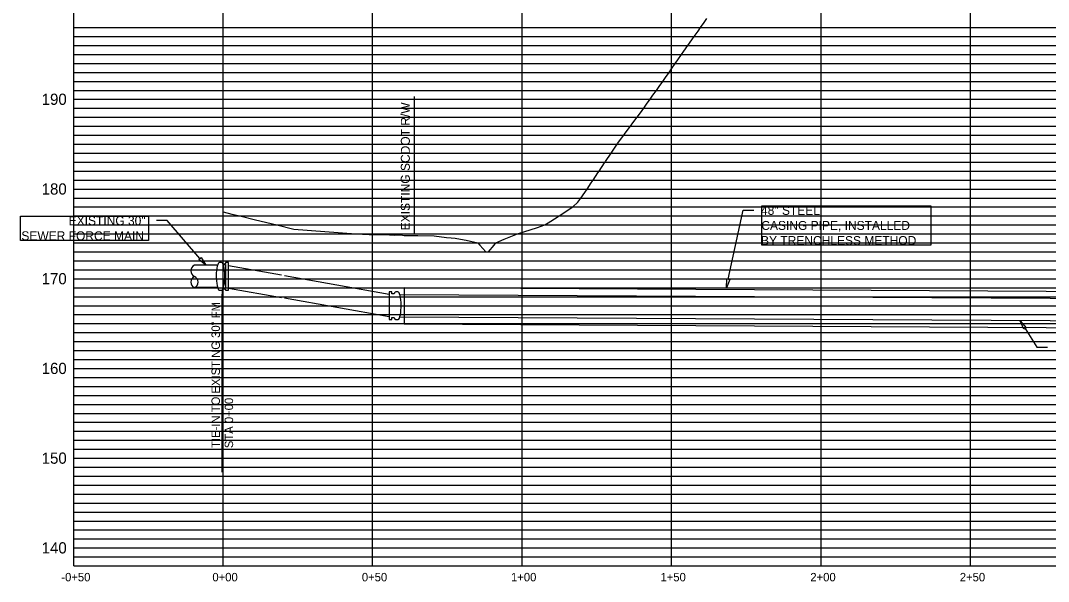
# Model space of a CAD drawing. Extents: x 1961446 to 1965364, y 798002 to 798458.
# Drawn here: x 1964684.5 to 1965028.3, y 798002.3 to 798189.8 of the extents above; entities that cross this region are included whole.
import ezdxf

# ---------------------------------------------------------------- set-up
doc = ezdxf.new("R2010")
doc.units = 0
for name, color, linetype in [('_C3D-PRSR-ANNO', 7, 'Continuous'), ('_C3D-PRSR-PIPE-NEW 30 FM', 7, 'Continuous'), ('C-ANNO-SUBT', 7, 'Continuous'), ('C-DOMW-MAIN-PIPE', 7, 'Continuous'), ('C-GRID-MEDI', 7, 'Continuous'), ('C-GRID-THIN', 7, 'Continuous'), ('C-PROF-EXST', 7, 'Continuous'), ('C-SSWR-FMAN-FTTG', 7, 'Continuous'), ('C-SSWR-FMAN-PIPE', 7, 'Continuous'), ('C-UTIL-FITT-ANNO', 7, 'Continuous'), ('RD_EX_RW', 7, 'Continuous')]:
    doc.layers.add(name, color=color, linetype=linetype)

msp = doc.modelspace()

# ---------------------------------------------------------------- linework, layer by layer
at = {"layer": '_C3D-PRSR-ANNO'}
for points in [[(1964750.23, 798108.01), (1964742.68, 798108.01)], [(1964750.32, 798100.51), (1964742.68, 798100.51)]]:
    msp.add_lwpolyline(points, dxfattribs=at)
for centre, start, end in [((1964743.5, 798106.14), 113.818, 246.182), ((1964743.5, 798102.39), 113.818, 246.182), ((1964741.85, 798102.39), 293.818, 66.182)]:
    msp.add_arc(centre, 2.05, start, end, dxfattribs=at)
at = {"layer": '_C3D-PRSR-PIPE-NEW 30 FM'}
msp.add_lwpolyline([(1964812.85, 798088.45), (1965222.8, 798086.11), (1965222.8, 798098.11), (1964812.85, 798100.45)], close=True, dxfattribs=at)
at = {"layer": 'C-DOMW-MAIN-PIPE'}
for points in [[(1964754.01, 798107.87), (1964771.76, 798104.74)], [(1964772.8, 798104.56), (1964807.75, 798098.38)], [(1964754.01, 798100.37), (1964771.76, 798097.24)], [(1964772.8, 798097.06), (1964807.75, 798090.88)]]:
    msp.add_lwpolyline(points, dxfattribs=at)
at = {"layer": 'C-GRID-MEDI'}
for points in [[(1964702.28, 798007.48), (1964702.28, 798313.48)], [(1964702.28, 798007.48), (1964702.28, 798313.48)], [(1964752.28, 798007.48), (1964752.28, 798313.48)], [(1964802.28, 798007.48), (1964802.28, 798313.48)], [(1964852.28, 798007.48), (1964852.28, 798313.48)], [(1964902.28, 798007.48), (1964902.28, 798313.48)], [(1964952.28, 798007.48), (1964952.28, 798313.48)], [(1965002.28, 798007.48), (1965002.28, 798313.48)], [(1964702.28, 798163.48), (1964752.28, 798163.48)], [(1964752.28, 798163.48), (1965283.11, 798163.48)], [(1964702.28, 798133.48), (1964752.28, 798133.48)], [(1964752.28, 798133.48), (1965283.11, 798133.48)], [(1964702.28, 798103.48), (1964752.28, 798103.48)], [(1964752.28, 798103.48), (1965283.11, 798103.48)], [(1964702.28, 798073.48), (1964752.28, 798073.48)], [(1964752.28, 798073.48), (1965283.11, 798073.48)], [(1964702.28, 798043.48), (1964752.28, 798043.48)], [(1964752.28, 798043.48), (1965283.11, 798043.48)], [(1964702.28, 798013.48), (1964752.28, 798013.48)], [(1964752.28, 798013.48), (1965283.11, 798013.48)], [(1964702.28, 798007.48), (1964752.28, 798007.48)], [(1964702.28, 798007.48), (1965352.28, 798007.48)], [(1964752.28, 798007.48), (1965283.11, 798007.48)]]:
    msp.add_lwpolyline(points, dxfattribs=at)
at = {"layer": 'C-GRID-THIN'}
for points in [[(1964702.28, 798187.48), (1964752.28, 798187.48)], [(1964752.28, 798187.48), (1965283.11, 798187.48)], [(1964702.28, 798184.48), (1964752.28, 798184.48)], [(1964752.28, 798184.48), (1965283.11, 798184.48)], [(1964702.28, 798181.48), (1964752.28, 798181.48)], [(1964752.28, 798181.48), (1965283.11, 798181.48)], [(1964702.28, 798178.48), (1964752.28, 798178.48)], [(1964752.28, 798178.48), (1965283.11, 798178.48)], [(1964702.28, 798175.48), (1964752.28, 798175.48)], [(1964752.28, 798175.48), (1965283.11, 798175.48)], [(1964702.28, 798172.48), (1964752.28, 798172.48)], [(1964752.28, 798172.48), (1965283.11, 798172.48)], [(1964702.28, 798169.48), (1964752.28, 798169.48)], [(1964752.28, 798169.48), (1965283.11, 798169.48)], [(1964702.28, 798166.48), (1964752.28, 798166.48)], [(1964752.28, 798166.48), (1965283.11, 798166.48)], [(1964702.28, 798160.48), (1964752.28, 798160.48)], [(1964752.28, 798160.48), (1965283.11, 798160.48)], [(1964702.28, 798157.48), (1964752.28, 798157.48)], [(1964752.28, 798157.48), (1965283.11, 798157.48)], [(1964702.28, 798154.48), (1964752.28, 798154.48)], [(1964752.28, 798154.48), (1965283.11, 798154.48)], [(1964702.28, 798151.48), (1964752.28, 798151.48)], [(1964752.28, 798151.48), (1965283.11, 798151.48)], [(1964702.28, 798148.48), (1964752.28, 798148.48)], [(1964752.28, 798148.48), (1965283.11, 798148.48)], [(1964702.28, 798145.48), (1964752.28, 798145.48)], [(1964752.28, 798145.48), (1965283.11, 798145.48)], [(1964702.28, 798142.48), (1964752.28, 798142.48)], [(1964702.28, 798139.48), (1964752.28, 798139.48)], [(1964752.28, 798142.48), (1965283.11, 798142.48)], [(1964752.28, 798139.48), (1965283.11, 798139.48)], [(1964702.28, 798136.48), (1964752.28, 798136.48)], [(1964752.28, 798136.48), (1965283.11, 798136.48)], [(1964702.28, 798130.48), (1964752.28, 798130.48)], [(1964752.28, 798130.48), (1965283.11, 798130.48)], [(1964702.28, 798127.48), (1964752.28, 798127.48)], [(1964752.28, 798127.48), (1965283.11, 798127.48)], [(1964702.28, 798124.48), (1964752.28, 798124.48)], [(1964752.28, 798124.48), (1965283.11, 798124.48)], [(1964702.28, 798121.48), (1964752.28, 798121.48)], [(1964752.28, 798121.48), (1965283.11, 798121.48)], [(1964702.28, 798118.48), (1964752.28, 798118.48)], [(1964702.28, 798115.48), (1964752.28, 798115.48)], [(1964752.28, 798118.48), (1965283.11, 798118.48)], [(1964752.28, 798115.48), (1965283.11, 798115.48)], [(1964702.28, 798112.48), (1964752.28, 798112.48)], [(1964752.28, 798112.48), (1965283.11, 798112.48)], [(1964702.28, 798109.48), (1964752.28, 798109.48)], [(1964752.28, 798109.48), (1965283.11, 798109.48)], [(1964702.28, 798106.48), (1964752.28, 798106.48)], [(1964752.28, 798106.48), (1965283.11, 798106.48)], [(1964702.28, 798100.48), (1964752.28, 798100.48)], [(1964752.28, 798100.48), (1965283.11, 798100.48)], [(1964702.28, 798097.48), (1964752.28, 798097.48)], [(1964702.28, 798094.48), (1964752.28, 798094.48)], [(1964752.28, 798097.48), (1965283.11, 798097.48)], [(1964752.28, 798094.48), (1965283.11, 798094.48)], [(1964702.28, 798091.48), (1964752.28, 798091.48)], [(1964752.28, 798091.48), (1965283.11, 798091.48)], [(1964702.28, 798088.48), (1964752.28, 798088.48)], [(1964752.28, 798088.48), (1965283.11, 798088.48)], [(1964702.28, 798085.48), (1964752.28, 798085.48)], [(1964752.28, 798085.48), (1965283.11, 798085.48)], [(1964702.28, 798082.48), (1964752.28, 798082.48)], [(1964752.28, 798082.48), (1965283.11, 798082.48)], [(1964702.28, 798079.48), (1964752.28, 798079.48)], [(1964752.28, 798079.48), (1965283.11, 798079.48)], [(1964702.28, 798076.48), (1964752.28, 798076.48)], [(1964752.28, 798076.48), (1965283.11, 798076.48)], [(1964702.28, 798070.48), (1964752.28, 798070.48)], [(1964752.28, 798070.48), (1965283.11, 798070.48)], [(1964702.28, 798067.48), (1964752.28, 798067.48)], [(1964752.28, 798067.48), (1965283.11, 798067.48)], [(1964702.28, 798064.48), (1964752.28, 798064.48)], [(1964752.28, 798064.48), (1965283.11, 798064.48)], [(1964702.28, 798061.48), (1964752.28, 798061.48)], [(1964752.28, 798061.48), (1965283.11, 798061.48)], [(1964702.28, 798058.48), (1964752.28, 798058.48)], [(1964752.28, 798058.48), (1965283.11, 798058.48)], [(1964702.28, 798055.48), (1964752.28, 798055.48)], [(1964752.28, 798055.48), (1965283.11, 798055.48)], [(1964702.28, 798052.48), (1964752.28, 798052.48)], [(1964752.28, 798052.48), (1965283.11, 798052.48)], [(1964702.28, 798049.48), (1964752.28, 798049.48)], [(1964702.28, 798046.48), (1964752.28, 798046.48)], [(1964752.28, 798049.48), (1965283.11, 798049.48)], [(1964752.28, 798046.48), (1965283.11, 798046.48)], [(1964702.28, 798040.48), (1964752.28, 798040.48)], [(1964752.28, 798040.48), (1965283.11, 798040.48)], [(1964702.28, 798037.48), (1964752.28, 798037.48)], [(1964752.28, 798037.48), (1965283.11, 798037.48)], [(1964702.28, 798034.48), (1964752.28, 798034.48)], [(1964752.28, 798034.48), (1965283.11, 798034.48)], [(1964702.28, 798031.48), (1964752.28, 798031.48)], [(1964752.28, 798031.48), (1965283.11, 798031.48)], [(1964702.28, 798028.48), (1964752.28, 798028.48)], [(1964752.28, 798028.48), (1965283.11, 798028.48)], [(1964702.28, 798025.48), (1964752.28, 798025.48)], [(1964702.28, 798022.48), (1964752.28, 798022.48)], [(1964752.28, 798025.48), (1965283.11, 798025.48)], [(1964752.28, 798022.48), (1965283.11, 798022.48)], [(1964702.28, 798019.48), (1964752.28, 798019.48)], [(1964752.28, 798019.48), (1965283.11, 798019.48)], [(1964702.28, 798016.48), (1964752.28, 798016.48)], [(1964752.28, 798016.48), (1965283.11, 798016.48)], [(1964702.28, 798010.48), (1964752.28, 798010.48)], [(1964752.28, 798010.48), (1965283.11, 798010.48)]]:
    msp.add_lwpolyline(points, dxfattribs=at)
at = {"layer": 'C-PROF-EXST'}
for points in [[(1964911.14, 798186.3), (1964911.97, 798187.48)], [(1964911.97, 798187.48), (1964913.14, 798189.15)], [(1964913.14, 798189.15), (1964914.08, 798190.48)], [(1964909.09, 798183.39), (1964909.86, 798184.48)], [(1964909.86, 798184.48), (1964911.14, 798186.3)], [(1964906.39, 798179.56), (1964907.75, 798181.48)], [(1964907.75, 798181.48), (1964909.09, 798183.39)], [(1964904.34, 798176.64), (1964905.64, 798178.48)], [(1964905.64, 798178.48), (1964906.39, 798179.56)], [(1964901.41, 798172.48), (1964902.27, 798173.7)], [(1964902.27, 798173.7), (1964903.52, 798175.48)], [(1964903.52, 798175.48), (1964904.34, 798176.64)], [(1964899.3, 798169.48), (1964900.19, 798170.75)], [(1964900.19, 798170.75), (1964901.41, 798172.48)], [(1964897.19, 798166.48), (1964898.11, 798167.79)], [(1964898.11, 798167.79), (1964899.3, 798169.48)], [(1964893.92, 798161.84), (1964895.08, 798163.48)], [(1964895.08, 798163.48), (1964896.02, 798164.82)], [(1964896.02, 798164.82), (1964897.19, 798166.48)], [(1964891.82, 798158.94), (1964892.97, 798160.48)], [(1964892.97, 798160.48), (1964893.92, 798161.84)], [(1964889.35, 798155.57), (1964890.79, 798157.48)], [(1964890.79, 798157.48), (1964891.82, 798158.94)], [(1964886.77, 798152.13), (1964888.54, 798154.48)], [(1964888.54, 798154.48), (1964889.35, 798155.57)], [(1964884.18, 798148.66), (1964886.29, 798151.48)], [(1964886.29, 798151.48), (1964886.77, 798152.13)], [(1964882.04, 798145.48), (1964884.03, 798148.44)], [(1964884.03, 798148.44), (1964884.06, 798148.48)], [(1964884.06, 798148.48), (1964884.18, 798148.66)], [(1964880.03, 798142.48), (1964880.19, 798142.73)], [(1964880.19, 798142.73), (1964882.04, 798145.48)], [(1964877.61, 798138.87), (1964878.02, 798139.48)], [(1964878.02, 798139.48), (1964879.87, 798142.24)], [(1964879.87, 798142.24), (1964880.03, 798142.48)], [(1964875.4, 798135.59), (1964876, 798136.48)], [(1964876, 798136.48), (1964877.61, 798138.87)], [(1964871.97, 798130.48), (1964873.24, 798132.38)], [(1964873.24, 798132.38), (1964873.99, 798133.48)], [(1964873.99, 798133.48), (1964875.4, 798135.59)], [(1964869.25, 798127.48), (1964870.86, 798129.11)], [(1964870.86, 798129.11), (1964871.97, 798130.48)], [(1964752.28, 798125.83), (1964755.18, 798125.13)], [(1964865.04, 798124.72), (1964869.25, 798127.48)], [(1964755.18, 798125.13), (1964757.83, 798124.48)], [(1964757.83, 798124.48), (1964763.1, 798123.2)], [(1964763.1, 798123.2), (1964770.19, 798121.48)], [(1964859.91, 798121.48), (1964861.04, 798122.19)], [(1964861.04, 798122.19), (1964863.98, 798124.03)], [(1964863.98, 798124.03), (1964864.68, 798124.48)], [(1964864.68, 798124.48), (1964865.04, 798124.72)], [(1964770.19, 798121.48), (1964775.92, 798120.09)], [(1964775.92, 798120.09), (1964796.66, 798118.48)], [(1964850.69, 798118.48), (1964857.44, 798120.66)], [(1964857.44, 798120.66), (1964859.91, 798121.48)], [(1964796.66, 798118.48), (1964801.07, 798118.29)], [(1964801.07, 798118.29), (1964807.96, 798118.2)], [(1964807.96, 798118.2), (1964809.48, 798118.11)], [(1964809.48, 798118.11), (1964809.64, 798118.12)], [(1964809.64, 798118.12), (1964812.27, 798118.04)], [(1964812.27, 798118.04), (1964812.82, 798117.98)], [(1964812.82, 798117.98), (1964817.4, 798117.96)], [(1964817.4, 798117.96), (1964822.88, 798117.89)], [(1964822.88, 798117.89), (1964827.02, 798117.28)], [(1964827.02, 798117.28), (1964828.53, 798117.17)], [(1964828.53, 798117.17), (1964829.89, 798117.1)], [(1964829.89, 798117.1), (1964832.88, 798116.52)], [(1964832.88, 798116.52), (1964833.6, 798116.4)], [(1964833.6, 798116.4), (1964837.51, 798115.48)], [(1964837.51, 798115.48), (1964838.14, 798114.77)], [(1964842.97, 798114.71), (1964843.52, 798115.48)], [(1964843.52, 798115.48), (1964846.25, 798116.7)], [(1964846.25, 798116.7), (1964850.69, 798118.48)], [(1964838.14, 798114.77), (1964840.16, 798112.48)], [(1964840.16, 798112.48), (1964840.54, 798112.46)], [(1964840.54, 798112.46), (1964840.81, 798112.45)], [(1964840.81, 798112.45), (1964840.91, 798112.45)], [(1964840.91, 798112.45), (1964841, 798112.48)], [(1964841, 798112.48), (1964842.97, 798114.71)]]:
    msp.add_lwpolyline(points, dxfattribs=at)
at = {"layer": 'C-SSWR-FMAN-FTTG'}
for points in [[(1964750.65, 798108.59), (1964750.46, 798108.18)], [(1964750.85, 798108.84), (1964750.65, 798108.59)], [(1964751.06, 798108.92), (1964750.85, 798108.84)], [(1964751.72, 798108.92), (1964751.06, 798108.92)], [(1964751.93, 798108.84), (1964751.72, 798108.92)], [(1964752.13, 798108.59), (1964751.93, 798108.84)], [(1964752.32, 798108.18), (1964752.13, 798108.59)], [(1964753.07, 798108.63), (1964752.28, 798108.28)], [(1964752.28, 798108.28), (1964753.07, 798108.28)], [(1964754.01, 798108.92), (1964753.07, 798108.92)], [(1964753.07, 798108.92), (1964753.07, 798108.63)], [(1964753.07, 798108.28), (1964753.07, 798108.28)], [(1964753.07, 798108.28), (1964753.07, 798104.27)], [(1964754.01, 798108.66), (1964754.01, 798108.92)], [(1964754.01, 798099.88), (1964754.01, 798108.66)], [(1964749.99, 798105.37), (1964749.96, 798104.5)], [(1964750.06, 798106.2), (1964749.99, 798105.37)], [(1964750.16, 798106.97), (1964750.06, 798106.2)], [(1964750.3, 798107.64), (1964750.16, 798106.97)], [(1964750.46, 798108.18), (1964750.3, 798107.64)], [(1964752.48, 798107.64), (1964752.32, 798108.18)], [(1964752.62, 798106.97), (1964752.48, 798107.64)], [(1964752.72, 798106.2), (1964752.62, 798106.97)], [(1964752.79, 798105.37), (1964752.72, 798106.2)], [(1964752.82, 798104.5), (1964752.79, 798105.37)], [(1964749.96, 798104.5), (1964749.97, 798103.61)], [(1964749.97, 798103.61), (1964750.02, 798102.75)], [(1964750.02, 798102.75), (1964750.11, 798101.95)], [(1964750.11, 798101.95), (1964750.23, 798101.23)], [(1964752.55, 798101.23), (1964752.67, 798101.95)], [(1964752.67, 798101.95), (1964752.76, 798102.75)], [(1964752.76, 798102.75), (1964752.81, 798103.61)], [(1964752.81, 798103.61), (1964752.82, 798104.5)], [(1964753.07, 798104.27), (1964753.07, 798100.27)], [(1964750.23, 798101.23), (1964750.38, 798100.62)], [(1964750.38, 798100.62), (1964750.55, 798100.14)], [(1964750.55, 798100.14), (1964750.75, 798099.81)], [(1964750.75, 798099.81), (1964750.95, 798099.65)], [(1964750.95, 798099.65), (1964751.06, 798099.65)], [(1964751.06, 798099.65), (1964751.06, 798099.63)], [(1964751.06, 798099.63), (1964751.72, 798099.63)], [(1964751.72, 798099.63), (1964751.72, 798099.65)], [(1964751.72, 798099.65), (1964751.83, 798099.65)], [(1964751.83, 798099.65), (1964752.03, 798099.81)], [(1964752.03, 798099.81), (1964752.23, 798100.14)], [(1964752.23, 798100.14), (1964752.4, 798100.62)], [(1964753.07, 798100.27), (1964752.28, 798100.27)], [(1964752.28, 798100.27), (1964753.07, 798099.92)], [(1964752.4, 798100.62), (1964752.55, 798101.23)], [(1964753.07, 798100.27), (1964753.07, 798100.27)], [(1964753.07, 798099.92), (1964753.07, 798099.63)], [(1964753.07, 798099.63), (1964754.01, 798099.63)], [(1964754.01, 798099.63), (1964754.01, 798099.88)], [(1964808.7, 798099.13), (1964807.75, 798099.13)], [(1964807.75, 798099.13), (1964807.75, 798098.87)], [(1964807.75, 798098.87), (1964807.75, 798090.09)], [(1964808.7, 798098.49), (1964808.7, 798099.13)], [(1964809.49, 798098.49), (1964808.7, 798098.49)], [(1964809.64, 798098.8), (1964809.49, 798098.49)], [(1964809.83, 798099.05), (1964809.64, 798098.8)], [(1964810.04, 798099.13), (1964809.83, 798099.05)], [(1964810.71, 798099.13), (1964810.04, 798099.13)], [(1964810.92, 798099.05), (1964810.71, 798099.13)], [(1964811.11, 798098.8), (1964810.92, 798099.05)], [(1964811.3, 798098.39), (1964811.11, 798098.8)], [(1964811.46, 798097.85), (1964811.3, 798098.39)], [(1964811.6, 798097.18), (1964811.46, 798097.85)], [(1964811.7, 798096.41), (1964811.6, 798097.18)], [(1964811.77, 798095.58), (1964811.7, 798096.41)], [(1964811.8, 798094.7), (1964811.77, 798095.58)], [(1964811.79, 798093.82), (1964811.8, 798094.7)], [(1964811.38, 798090.83), (1964811.54, 798091.44)], [(1964811.54, 798091.44), (1964811.66, 798092.16)], [(1964811.66, 798092.16), (1964811.74, 798092.96)], [(1964811.74, 798092.96), (1964811.79, 798093.82)], [(1964807.75, 798090.09), (1964807.75, 798089.84)], [(1964807.75, 798089.84), (1964808.7, 798089.84)], [(1964808.7, 798089.84), (1964808.7, 798090.48)], [(1964808.7, 798090.48), (1964809.5, 798090.48)], [(1964809.5, 798090.48), (1964809.54, 798090.35)], [(1964809.54, 798090.35), (1964809.73, 798090.02)], [(1964809.73, 798090.02), (1964809.94, 798089.86)], [(1964809.94, 798089.86), (1964810.04, 798089.86)], [(1964810.04, 798089.86), (1964810.04, 798089.84)], [(1964810.04, 798089.84), (1964810.71, 798089.84)], [(1964810.71, 798089.84), (1964810.71, 798089.86)], [(1964810.71, 798089.86), (1964810.81, 798089.86)], [(1964810.81, 798089.86), (1964811.02, 798090.02)], [(1964811.02, 798090.02), (1964811.21, 798090.35)], [(1964811.21, 798090.35), (1964811.38, 798090.83)]]:
    msp.add_lwpolyline(points, dxfattribs=at)
at = {"layer": 'C-SSWR-FMAN-PIPE'}
for points in [[(1964811.35, 798098.23), (1965226.74, 798095.86)], [(1964811.35, 798090.73), (1965226.74, 798088.36)]]:
    msp.add_lwpolyline(points, dxfattribs=at)
at = {"layer": 'C-UTIL-FITT-ANNO'}
for points in [[(1964921.25, 798103.39), (1964926.22, 798126.38)], [(1964926.22, 798126.38), (1964929.8, 798126.38)], [(1964733.57, 798122.93), (1964729.98, 798122.93)], [(1964744.49, 798110.28), (1964733.57, 798122.93)], [(1964751.99, 798099.63), (1964751.99, 798038.76)], [(1964751.99, 798038.76), (1964751.99, 798098.35)], [(1965020.51, 798086.85), (1965024.45, 798080.6)], [(1965024.45, 798080.6), (1965028.04, 798080.6)]]:
    msp.add_lwpolyline(points, dxfattribs=at)
for points in [[(1964932.5, 798127.91), (1964988.99, 798127.91), (1964988.99, 798114.71), (1964932.5, 798114.71)], [(1964684.51, 798124.45), (1964727.28, 798124.45), (1964727.28, 798116.3), (1964684.51, 798116.3)], [(1964744.87, 798110.61), (1964746.45, 798108.01), (1964744.11, 798109.96)], [(1964921.74, 798103.28), (1964920.62, 798100.45), (1964920.76, 798103.49)], [(1965020.09, 798086.59), (1965018.91, 798089.39), (1965020.93, 798087.12)]]:
    msp.add_lwpolyline(points, close=True, dxfattribs=at)
at = {"layer": 'RD_EX_RW'}
msp.add_lwpolyline([(1964816.28, 798118.69), (1964816.28, 798164.37)], dxfattribs=at)

# ---------------------------------------------------------------- texts
at = {"layer": 'C-ANNO-SUBT'}
for s, height, p in [('190', 3.75, (1964691.58, 798161.63)), ('180', 3.75, (1964691.58, 798131.63)), ('170', 3.75, (1964691.58, 798101.63)), ('160', 3.75, (1964691.58, 798071.63)), ('150', 3.75, (1964691.58, 798041.63)), ('140', 3.75, (1964691.58, 798011.63)), ('-0+50', 2.814, (1964698.14, 798002.31)), ('0+00', 2.814, (1964748.67, 798002.31)), ('0+50', 2.814, (1964798.67, 798002.31)), ('1+00', 2.814, (1964848.56, 798002.31)), ('1+50', 2.814, (1964898.56, 798002.31)), ('2+00', 2.814, (1964948.68, 798002.31)), ('2+50', 2.814, (1964998.68, 798002.31))]:
    msp.add_text(s, height=height, rotation=360, dxfattribs=at).set_placement(p)
at = {"layer": 'C-UTIL-FITT-ANNO'}
for s, p in [('48" STEEL', (1964932.18, 798124.85)), ('EXISTING 30"', (1964700.6, 798121.4)), ('CASING PIPE, INSTALLED', (1964932.29, 798119.81)), ('SEWER FORCE MAIN', (1964684.78, 798116.35)), ('BY TRENCHLESS METHOD', (1964932.2, 798114.76))]:
    msp.add_text(s, height=3, dxfattribs=at).set_placement(p)
for s, p in [('TIE-IN TO EXISTING 30" FM', (1964751.19, 798046.92)), ('STA 0+00', (1964755.6, 798046.84))]:
    msp.add_text(s, height=2.814, rotation=90, dxfattribs=at).set_placement(p)
at = {"layer": 'RD_EX_RW'}
msp.add_text('EXISTING SCDOT R/W', height=3, rotation=90, dxfattribs=at).set_placement((1964814.71, 798119.67))

doc.saveas('drawing.dxf')
